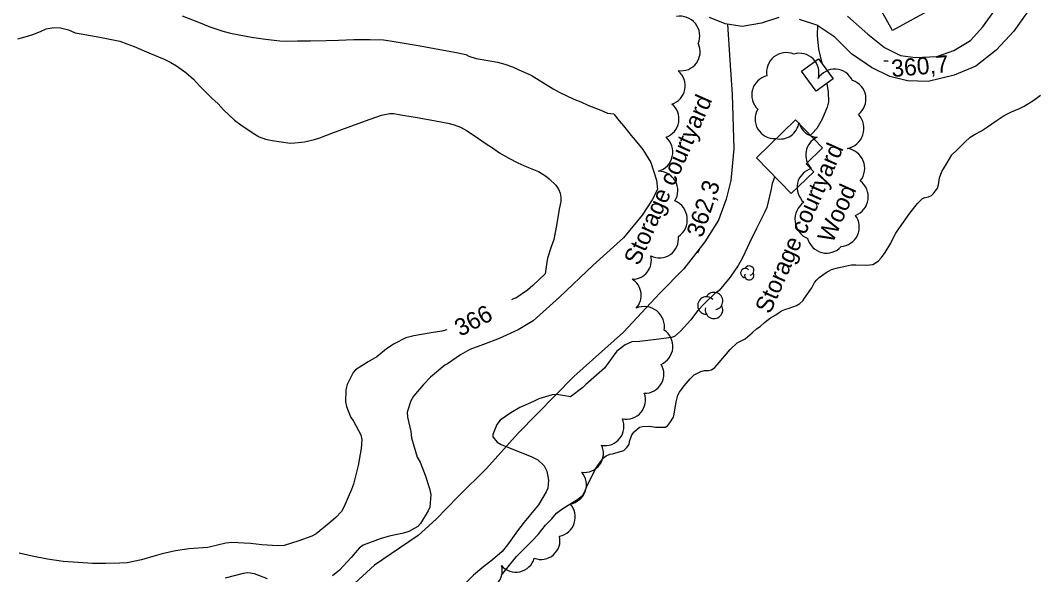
# Model space of a CAD drawing. Extents: x 287698 to 290158, y 5234163 to 5237182.
# Drawn here: x 288812.3 to 288989.7, y 5234475.2 to 5234572.2 of the extents above; entities that cross this region are included whole.
import ezdxf

# ---------------------------------------------------------------- set-up
doc = ezdxf.new("R2010")
doc.units = 0
for name, color, linetype in [('Niveau 19', 7, 'Continuous'), ('Niveau 2', 7, 'Continuous'), ('Niveau 22', 7, 'Continuous'), ('Niveau 3', 7, 'Continuous'), ('Niveau 31', 7, 'Continuous'), ('Niveau 4', 7, 'Continuous'), ('Niveau 44', 7, 'Continuous'), ('Niveau 57', 7, 'Continuous')]:
    doc.layers.add(name, color=color, linetype=linetype)

msp = doc.modelspace()

# ---------------------------------------------------------------- linework, layer by layer
at = {"layer": 'Niveau 19'}
for points in [[(288956.91, 5234572.88), (288960.47, 5234569.74), (288963.39, 5234567.37), (288966.17, 5234565.97), (288968.79, 5234565.65), (288972.52, 5234565.81), (288975.51, 5234566.88), (288978.42, 5234568.64), (288980.58, 5234571.02), (288982.82, 5234574.12)], [(288944.91, 5234572.66), (288941.87, 5234571.68), (288938.52, 5234571.09), (288935.51, 5234571.56), (288932.8, 5234572.67)], [(288988.3, 5234573.46), (288986.03, 5234570.25), (288982.93, 5234566.93), (288979.33, 5234564.14), (288975.56, 5234562.57), (288971.02, 5234561.46), (288967.39, 5234561.59), (288964.32, 5234562.3), (288961.09, 5234563.88), (288957.6, 5234566.3), (288954.68, 5234569.22), (288951.57, 5234571.31), (288948.5, 5234572.31)]]:
    msp.add_lwpolyline(points, dxfattribs=at)
at = {"layer": 'Niveau 2'}
for points in [[(288840.55, 5234572.95), (288843.44, 5234571.83), (288845.41, 5234571.01), (288847.68, 5234570.26), (288849.04, 5234569.92), (288850.52, 5234569.62), (288852.7, 5234569.23), (288855.15, 5234568.85), (288857.66, 5234568.54), (288858.74, 5234568.52), (288860.76, 5234568.58), (288863.01, 5234568.59), (288865.76, 5234568.61), (288867.93, 5234568.69), (288870.59, 5234568.78), (288873.4, 5234568.78), (288875.78, 5234568.71), (288876.93, 5234568.58), (288879.38, 5234568.16), (288882.19, 5234567.67), (288885.61, 5234567.06), (288888.55, 5234566.55), (288890.17, 5234566.17), (288890.67, 5234565.91), (288891.95, 5234565.49), (288893, 5234565.3), (288895.68, 5234564.82), (288897.01, 5234564.46), (288898.33, 5234564), (288899.44, 5234563.52), (288901.6, 5234562.53), (288902.97, 5234561.66), (288905.43, 5234560.14), (288906.5, 5234559.6), (288909.03, 5234558.38), (288910.27, 5234557.92), (288911.49, 5234557.34), (288913.75, 5234556.43), (288914.92, 5234555.89), (288916.04, 5234555.81), (288916.04, 5234555.81)], [(288811.81, 5234568.89), (288813.13, 5234569.24), (288814.44, 5234569.68), (288815.76, 5234570.2), (288816.78, 5234570.68), (288818.18, 5234570.92), (288819.3, 5234570.83), (288820.69, 5234570.46), (288820.69, 5234570.46)], [(288820.69, 5234570.46), (288821.86, 5234569.97), (288822.87, 5234569.79), (288826.15, 5234569.21), (288829.67, 5234568.48), (288830.9, 5234568.06), (288832.14, 5234567.56), (288834.76, 5234566.47), (288837.44, 5234565.33), (288838.59, 5234564.77), (288839.58, 5234564.19), (288841.22, 5234563.04), (288842.53, 5234561.88), (288843.62, 5234560.68), (288845.75, 5234558.54), (288846.83, 5234557.55), (288847.81, 5234556.52), (288849.71, 5234554.7), (288850.84, 5234553.9), (288852.97, 5234552.4), (288854, 5234551.78), (288855.12, 5234551.37), (288856.29, 5234551.16), (288859.45, 5234550.68), (288860.28, 5234550.7), (288861.97, 5234550.91), (288863.68, 5234551.29), (288864.65, 5234551.61), (288866.75, 5234552.42), (288869.59, 5234553.44), (288872.63, 5234554.56), (288875.45, 5234555.57), (288876.87, 5234555.86), (288877.58, 5234555.86), (288878.82, 5234555.64), (288881.99, 5234555.08), (288884.87, 5234554.57), (288887.03, 5234554.15), (288888.14, 5234553.85), (288889.24, 5234553.48), (288890.31, 5234552.89), (288891.44, 5234552.13), (288893.7, 5234550.56), (288894.83, 5234549.85), (288896.06, 5234549), (288897.56, 5234548.08), (288899.26, 5234547.21), (288900.83, 5234546.52), (288902.9, 5234545.69), (288904.13, 5234544.94), (288904.73, 5234544.44), (288905.91, 5234543.3), (288906.37, 5234542.64), (288906.68, 5234541.93), (288906.8, 5234541.21), (288906.77, 5234540.49), (288906.52, 5234539.1), (288906.02, 5234536.26), (288905.54, 5234533.82), (288905.09, 5234532.52), (288904.48, 5234530.55), (288904.26, 5234529.44), (288904.07, 5234527.84)], [(288951.64, 5234571.29), (288951.59, 5234569.5), (288951.86, 5234567.13), (288952.41, 5234564.68)], [(288953.31, 5234561.13), (288953.56, 5234559.66), (288953.57, 5234557.89), (288953.35, 5234556.95), (288952.46, 5234554.86), (288951.54, 5234553.23), (288950.74, 5234552.33), (288950.43, 5234552.06)], [(288916.04, 5234555.81), (288916.13, 5234555.67), (288916.98, 5234554.6), (288917.72, 5234553.67), (288918.46, 5234552.84), (288919.06, 5234552.02), (288919.8, 5234551.19), (288921.14, 5234549.55), (288922.5, 5234547.31), (288923.54, 5234544.17), (288923.68, 5234542.54), (288922.73, 5234540.77), (288921.03, 5234538.1), (288917.72, 5234534.11), (288912.46, 5234529.31), (288906.55, 5234523.72), (288901.93, 5234519.58), (288899.34, 5234518), (288895.98, 5234516.52), (288893.27, 5234515.48), (288890.89, 5234514.56), (288889.26, 5234513.66), (288886.98, 5234512.1), (288886.48, 5234511.82), (288884.01, 5234509.77), (288882.74, 5234508.48), (288881.02, 5234506.42), (288880.54, 5234505.62), (288879.92, 5234503.63)], [(288944.2, 5234544.82), (288943.74, 5234543.63), (288943.5, 5234542.37), (288942.79, 5234539.41), (288942.42, 5234538.57), (288940.98, 5234535.75), (288939.72, 5234533.1), (288938.64, 5234530.72), (288937.79, 5234529.27), (288936.39, 5234527.25), (288934.45, 5234524.91), (288933.72, 5234524.38), (288931.88, 5234522.65), (288930.7, 5234521.32), (288929.52, 5234519.76), (288927.71, 5234517.77), (288926.68, 5234516.84), (288926.12, 5234516.71), (288923.45, 5234516.35), (288920.55, 5234515.96), (288919.21, 5234515.92), (288918.04, 5234515.4), (288916.58, 5234514.29), (288915.91, 5234513.42), (288914.4, 5234511.35), (288913.51, 5234510.52), (288911.13, 5234508.47), (288910.64, 5234507.93), (288908.49, 5234506.33), (288908.17, 5234506.38), (288906.08, 5234506.7), (288905.24, 5234506.66), (288902.94, 5234505.95), (288902, 5234505.52), (288899.59, 5234504.44), (288898.02, 5234503.53), (288896.19, 5234502.24), (288895.61, 5234501.49), (288894.88, 5234499.74), (288894.9, 5234499.29), (288895.63, 5234498.38), (288896.37, 5234497.98), (288899.11, 5234496.87), (288901.6, 5234495.9), (288902.76, 5234495.32), (288903.84, 5234494.22), (288904.31, 5234493.29), (288904.62, 5234491.71), (288904.49, 5234490.35), (288904.22, 5234489.72)], [(288904.07, 5234527.84), (288901.9, 5234525.78), (288900.95, 5234524.97), (288898.91, 5234523.59), (288898.61, 5234523.53), (288898.14, 5234523.28)], [(288886.87, 5234518), (288885.95, 5234517.8), (288884.13, 5234517.51), (288881.08, 5234517), (288879.67, 5234516.61), (288877.64, 5234515.56), (288876.31, 5234514.68), (288874.58, 5234513.32), (288873.11, 5234512.41), (288870.88, 5234511.04), (288870.44, 5234510.54), (288869.44, 5234508.47), (288869.2, 5234507.54), (288869.14, 5234505.46), (288869.31, 5234504.63), (288870.02, 5234502.84)], [(288879.92, 5234503.63), (288879.95, 5234502.78), (288880.55, 5234500.22), (288880.67, 5234499.13), (288881.66, 5234495.77), (288882.18, 5234494.88), (288883.05, 5234492.61), (288883.82, 5234490.27), (288884.05, 5234489.22), (288883.85, 5234486.99), (288883.58, 5234486.35), (288882.27, 5234484.16), (288881.79, 5234483.65), (288880.23, 5234482.76), (288879.29, 5234482.47), (288876.75, 5234481.92), (288875.17, 5234481.46), (288872.21, 5234480.37), (288871.52, 5234479.87), (288870.11, 5234478.23), (288868.06, 5234476.02), (288866.86, 5234475.01)], [(288870.02, 5234502.84), (288870.53, 5234502.05), (288871.79, 5234499.65), (288872, 5234498.86), (288871.84, 5234497.27), (288871.33, 5234494.33), (288870.54, 5234491.06), (288870.19, 5234490.11), (288868.83, 5234487.02), (288868.41, 5234486.28), (288867.42, 5234485.18), (288866.28, 5234484.24), (288864.01, 5234482.35), (288863.23, 5234481.95), (288860.99, 5234481.14), (288858.38, 5234480.34), (288857.29, 5234480.26), (288854.49, 5234480.42), (288852.53, 5234480.66), (288849.22, 5234480.86), (288848.17, 5234480.7), (288845.28, 5234480.03), (288845.04, 5234479.97)], [(288904.22, 5234489.72), (288902.86, 5234487.43), (288902.32, 5234486.72), (288900.37, 5234484.41), (288899.19, 5234482.89), (288897.48, 5234480.44), (288896.52, 5234479.24), (288894.84, 5234477.8), (288893.3, 5234476.66), (288891.52, 5234475.12), (288890.08, 5234473.69), (288888.48, 5234472.54), (288886.83, 5234471.58), (288885.23, 5234470.96), (288883, 5234470.3), (288880.34, 5234469.66), (288877.91, 5234469.23), (288875.04, 5234468.77), (288873.9, 5234468.39), (288871.08, 5234467.46), (288870.81, 5234467.3)], [(288845.04, 5234479.97), (288841.74, 5234479.71), (288839.37, 5234479.37), (288837.05, 5234478.87), (288835.86, 5234478.49), (288833.47, 5234477.83), (288830.92, 5234477.31), (288829.63, 5234477.22), (288827.17, 5234477.15), (288824.87, 5234477.17), (288822.38, 5234477.32), (288819.78, 5234477.53), (288817.02, 5234477.92), (288814.34, 5234478.42), (288812.04, 5234478.97)], [(288855.51, 5234474.46), (288853.22, 5234475.33), (288852.02, 5234475.55), (288851.24, 5234475.4), (288848.11, 5234474.58)]]:
    msp.add_lwpolyline(points, dxfattribs=at)
at = {"layer": 'Niveau 22'}
msp.add_lwpolyline([(288935.95, 5234571.49), (288936.33, 5234565.17), (288936.75, 5234559.19), (288937.03, 5234549.7), (288936.5, 5234544.12), (288935.68, 5234540.86), (288934.34, 5234537.19), (288931.95, 5234533.41), (288928.31, 5234528.71), (288924.11, 5234524.44), (288917.75, 5234517.64), (288909.03, 5234509.89), (288899.3, 5234499.95), (288893.8, 5234493.75), (288888.8, 5234488.87), (288884.99, 5234484.89), (288881.83, 5234482.07), (288878.56, 5234479.87), (288874.22, 5234476.9), (288870.03, 5234473.11)], dxfattribs=at)
at = {"layer": 'Niveau 3'}
for p, q in [((288963.25, 5234565.04), (288964.05, 5234565.04)), ((288930.75, 5234531.48), (288931.07, 5234532.21))]:
    msp.add_line(p, q, dxfattribs=at)
at = {"layer": 'Niveau 31'}
for points in [[(288974.46, 5234575.71), (288964.79, 5234570.35), (288961.22, 5234576.81), (288958, 5234575.03), (288956.35, 5234578.02), (288963.79, 5234582.14), (288962.43, 5234584.59), (288966.91, 5234587.06), (288968, 5234585.09), (288968.96, 5234585.62)], [(288951.44, 5234559.76), (288948.88, 5234563.27), (288951.85, 5234565.44), (288954.41, 5234561.93)], [(288941.02, 5234548.11), (288947.84, 5234554.73), (288952.56, 5234549.86), (288949.67, 5234547.06), (288951.01, 5234545.68), (288947.07, 5234541.86)]]:
    msp.add_lwpolyline(points, close=True, dxfattribs=at)
at = {"layer": 'Niveau 4'}
for points in [[(288985.61, 5234556.15), (288987.01, 5234556.71), (288987.8, 5234557.16), (288989.48, 5234558.17), (288990.67, 5234559.05)], [(288905.23, 5234485), (288906.03, 5234485.94), (288906.7, 5234486.51), (288907.48, 5234487.04), (288909.68, 5234488.36), (288910.65, 5234489.14), (288910.96, 5234489.74), (288911.42, 5234490.94), (288912.14, 5234492.29), (288912.7, 5234493.51), (288913.17, 5234494.22), (288914.31, 5234495.71), (288914.71, 5234496.02), (288915.34, 5234496.26), (288915.84, 5234496.35), (288917.78, 5234496.95), (288918.28, 5234497.39), (288918.71, 5234497.98), (288918.82, 5234498.51), (288919.19, 5234499.68), (288919.61, 5234500.2), (288920.56, 5234500.98), (288921.07, 5234501.1), (288922.28, 5234501.17), (288923.32, 5234500.98), (288925.07, 5234500.98), (288925.47, 5234501.3), (288925.82, 5234501.76), (288926.48, 5234502.74), (288926.59, 5234503.27), (288926.97, 5234505.46), (288927.24, 5234506.59), (288927.53, 5234507.11), (288928.34, 5234508.22), (288929.38, 5234509.44), (288930.12, 5234510.16), (288931.24, 5234510.76), (288931.88, 5234510.91), (288932.61, 5234510.9), (288933.14, 5234511.05), (288933.7, 5234511.44), (288934.5, 5234512.32), (288936.42, 5234514.58), (288937.63, 5234515.78), (288938.11, 5234515.96), (288939.01, 5234516.48), (288940.24, 5234517.48), (288941, 5234518.2), (288941.62, 5234518.61), (288942.39, 5234519.31), (288943.45, 5234520.12), (288944.4, 5234520.64), (288945.39, 5234521.32), (288945.97, 5234521.61), (288946.69, 5234521.8), (288948, 5234522.28), (288948.58, 5234522.63), (288949.13, 5234523.1), (288949.41, 5234523.54), (288950.69, 5234525.38), (288951.16, 5234526.28), (288951.53, 5234526.78), (288951.94, 5234527.15), (288953.18, 5234528.07), (288954.12, 5234528.56), (288955.15, 5234528.86), (288957.64, 5234529.42), (288958.35, 5234529.41), (288960.28, 5234529.32), (288961.36, 5234529.45), (288962.28, 5234530.02), (288962.88, 5234530.69), (288963.48, 5234531.54), (288964.52, 5234533.18), (288964.76, 5234533.83), (288965.35, 5234534.92), (288966.03, 5234535.86), (288966.69, 5234536.86), (288967.82, 5234538.41), (288969.15, 5234540.1), (288970.06, 5234540.98), (288970.52, 5234541.18), (288971.07, 5234541.29), (288971.59, 5234541.52), (288971.98, 5234541.88), (288972.67, 5234542.79), (288972.82, 5234543.37), (288973.03, 5234544.6), (288973.39, 5234545.73), (288973.72, 5234546.18), (288974.33, 5234547.25), (288975.19, 5234548.64), (288976.11, 5234549.5), (288977.46, 5234550.82), (288978.36, 5234551.7), (288979.27, 5234552.25), (288980.37, 5234552.83), (288981.4, 5234553.5), (288982.9, 5234554.59), (288984.34, 5234555.5), (288985.61, 5234556.15)], [(288896.43, 5234475.14), (288897.34, 5234476.28), (288899.05, 5234478.4), (288899.99, 5234479.33), (288901.79, 5234481.12), (288902.82, 5234482.26), (288904.13, 5234483.84), (288905.23, 5234485)]]:
    msp.add_lwpolyline(points, dxfattribs=at)
at = {"layer": 'Niveau 44'}
for centre, radius, start, end in [((288939.04, 5234527.97), 0.814, 44.1154, 269.804), ((288939.74, 5234527.56), 0.814, 166.9369, 29.6212), ((288939.74, 5234528.38), 0.814, 282.2692, 149.7263), ((288933.57, 5234523.05), 1.53, 282.2692, 149.7263), ((288932.25, 5234522.28), 1.53, 44.1154, 269.804), ((288933.57, 5234521.52), 1.53, 166.9369, 29.6212)]:
    msp.add_arc(centre, radius, start, end, dxfattribs=at)
for centre, major_axis, ratio, start_param, end_param in [((288927.54, 5234569.34), (2.8, 2.2), 0.987377, 5.241214, 7.347717), ((288927.8, 5234566.65), (3.33, 0.31), 0.995599, 4.476514, 6.627109), ((288946.18, 5234563.08), (-2.66, -2.15), 0.998749, 3.634783, 5.789995), ((288948.51, 5234562.97), (-2.42, 2.41), 0.999862, 3.630834, 5.793944), ((288925.22, 5234560.7), (0.65, 3.27), 0.99868, 3.635348, 5.78943), ((288954.69, 5234560.2), (-3.41, 0.2), 0.998756, 3.632221, 5.792557), ((288943.59, 5234559.11), (-0.91, -3.3), 0.999613, 3.636559, 5.788219), ((288956.73, 5234558.39), (3.19, 1.22), 0.99993, 5.010299, 7.170318), ((288924.07, 5234554.9), (3.26, -0.87), 0.999474, 5.308937, 7.431125), ((288944.17, 5234554.89), (1.76, -2.94), 0.99986, 3.637675, 5.787103), ((288956.18, 5234553.27), (3.42, -1.13), 0.997771, 5.216471, 7.345098), ((288945.07, 5234554.81), (2.24, 2.59), 0.999012, 3.63586, 5.263854), ((288951.76, 5234555.09), (-2.8, -1.95), 0.989288, 5.920333, 7.198141), ((288922.86, 5234549.11), (3.41, -0.76), 0.999914, 5.218071, 7.346524), ((288953.03, 5234548.61), (-3.31, -0.86), 0.999235, 4.89566, 6.802657), ((288956.3, 5234546.21), (3.37, 1.38), 0.975298, 5.235956, 7.323812), ((288923.82, 5234542.35), (2.98, 1.71), 0.991463, 5.213764, 7.328066), ((288951.51, 5234542.93), (-2.6, -2.22), 0.999542, 4.281756, 6.43864), ((288957.05, 5234541.28), (3.43, -0.63), 0.998337, 5.266782, 7.387003), ((288925.32, 5234537.29), (3.55, -0.5), 0.999934, 5.45345, 7.585003), ((288951.4, 5234537.35), (-3.66, -0.29), 0.996308, 5.250271, 7.369054), ((288955.56, 5234536.01), (-0.54, 3.38), 0.99927, 3.036482, 5.189535), ((288924.02, 5234533.96), (2.74, 1.92), 0.998018, 3.638055, 5.786723), ((288953.26, 5234534.86), (2.75, 2.04), 0.997904, 2.758778, 4.910647), ((288919.3, 5234530.18), (3.17, -1.01), 0.991259, 5.006042, 6.836099), ((288917.51, 5234524.04), (2.41, 2.3), 0.997618, 4.783733, 6.542581), ((288921.36, 5234518.53), (2.41, 2.62), 0.999427, 5.29849, 7.429348), ((288922.94, 5234515.13), (3.42, -0.31), 0.999728, 5.219945, 7.347631), ((288921.44, 5234510.28), (2.91, -1.68), 0.998324, 5.217768, 7.343734), ((288918.23, 5234505.75), (2.1, -2.62), 0.999879, 5.403919, 7.53542), ((288914.49, 5234501.12), (0.74, 3.26), 0.997718, 3.193466, 5.346769), ((288910.9, 5234496.44), (1.98, 2.69), 0.998027, 3.636937, 5.787841), ((288907.88, 5234490.92), (3.18, -1.15), 0.99903, 5.214247, 7.342295), ((288905.91, 5234485.28), (3.23, -1.06), 0.999909, 5.222455, 7.348702), ((288903.31, 5234481.21), (0.72, 3.26), 0.997021, 2.997693, 5.150577), ((288898.92, 5234478.98), (3.16, 1.07), 0.998006, 3.52392, 5.684867), ((288893.22, 5234475.89), (2.4, 2.31), 0.998033, 3.635237, 5.789541)]:
    msp.add_ellipse(centre, major_axis=major_axis, ratio=ratio, start_param=start_param, end_param=end_param, dxfattribs=at)

# ---------------------------------------------------------------- texts
at = {"layer": 'Niveau 2'}
msp.add_text('366', height=3, rotation=27.6815, dxfattribs=at).set_placement((288889.2, 5234516.78))
at = {"layer": 'Niveau 3'}
for s, rotation, p in [('360,7', 4.9366, (288964.7, 5234562.22)), ('362,3', 71.81, (288931.53, 5234534.01))]:
    msp.add_text(s, height=3, rotation=rotation, dxfattribs=at).set_placement(p)
at = {"layer": 'Niveau 44'}
msp.add_text('Wood', height=3, rotation=66.1217, dxfattribs=at).set_placement((288954.3, 5234533.03))
at = {"layer": 'Niveau 57'}
for p in [(288920.43, 5234529.1), (288943.37, 5234520.65)]:
    msp.add_text('Storage courtyard', height=3, rotation=66.1217, dxfattribs=at).set_placement(p)

doc.saveas('drawing.dxf')
